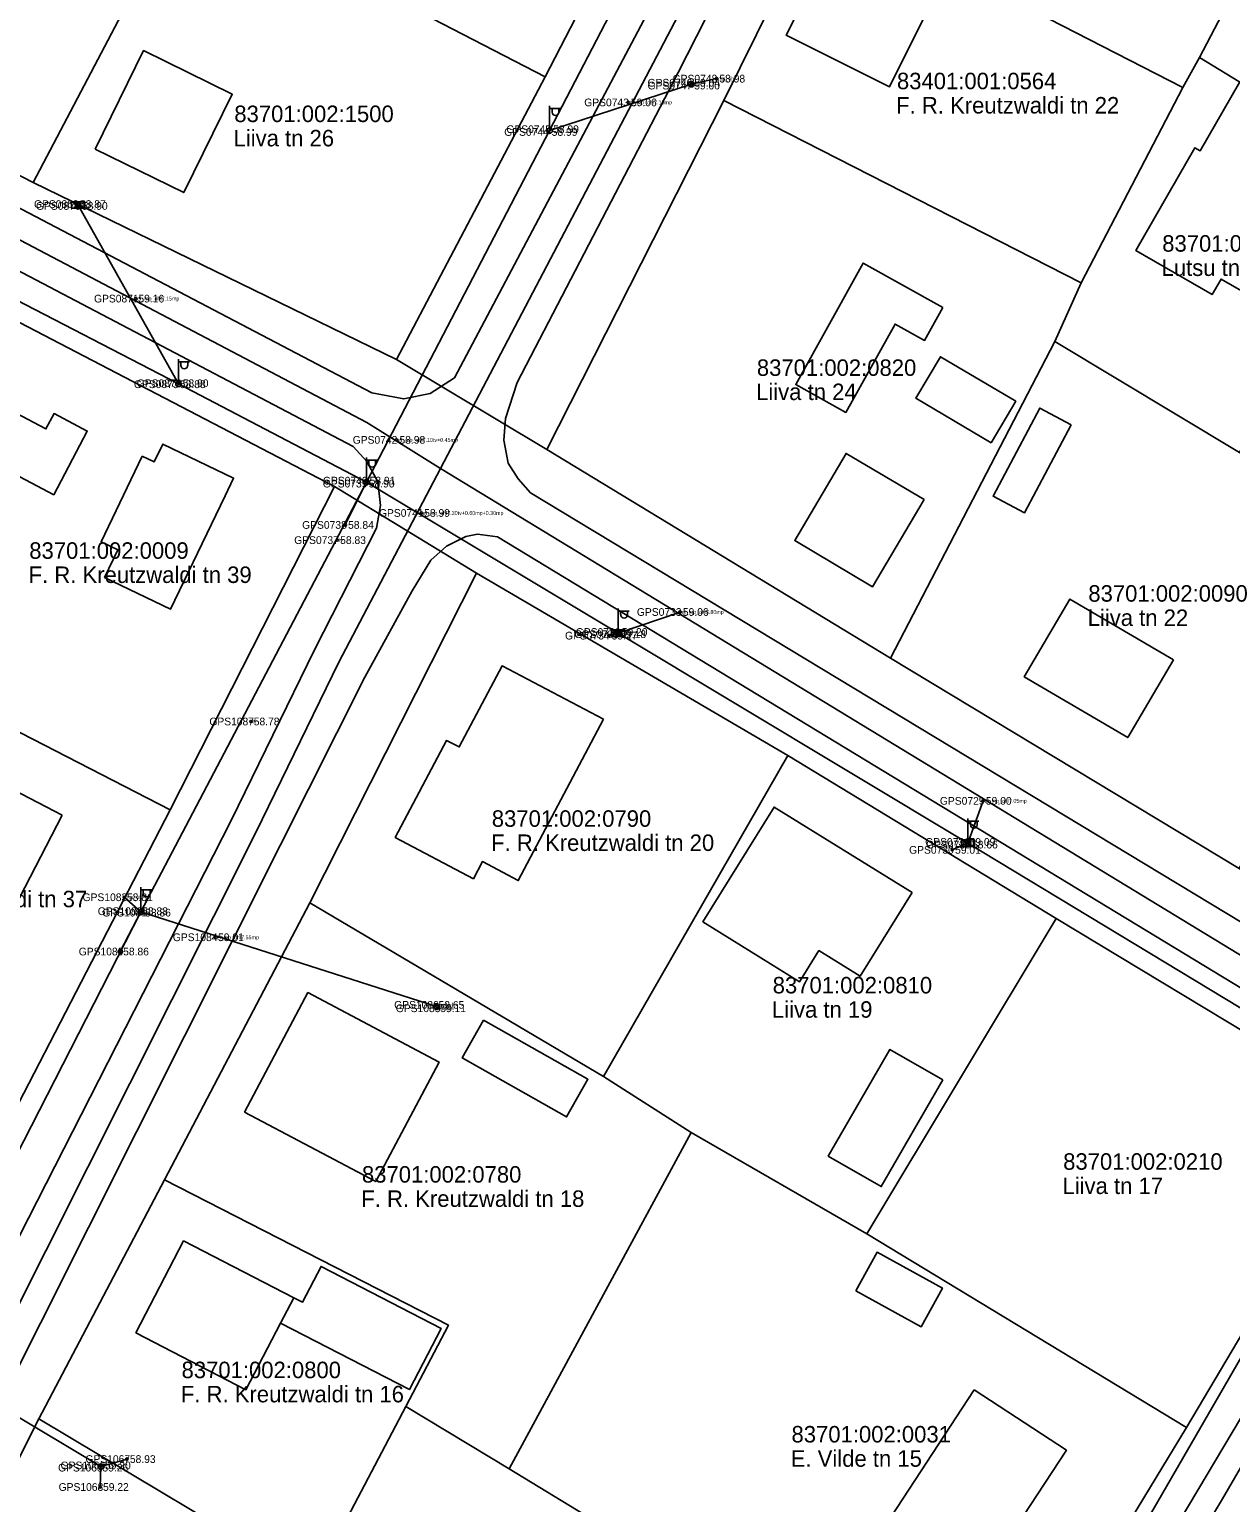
# Model space of a CAD drawing. Extents: x 580119 to 583377, y 6518915 to 6520820.
# Drawn here: x 581663.4 to 581772.7, y 6520226.6 to 6520360.6 of the extents above; entities that cross this region are included whole.
import ezdxf

# ---------------------------------------------------------------- set-up
doc = ezdxf.new("R2010")
doc.units = 0
for name, color, linetype in [('ELRAJATISMP', 7, 'Continuous'), ('Hoone Elu- või ühiskondlik hoone', 7, 'Continuous'), ('Hoone Kõrval- või tootmishoone', 7, 'Continuous'), ('L_AADRESS', 7, 'Continuous'), ('MAAMUDEL', 7, 'Continuous'), ('MOOTKORG-EH2000', 7, 'Continuous'), ('MOOTMPUNKT', 7, 'Continuous'), ('MOOTNR', 7, 'Continuous'), ('MPOHULIIN', 7, 'Continuous'), ('Muu rajatis Katusealune', 7, 'Continuous'), ('PIIR', 7, 'Continuous'), ('POST', 7, 'Continuous'), ('Rippe kõrgus', 7, 'Continuous'), ('Tee Liiklusala', 7, 'Continuous'), ('Tee Tänav Püsikate', 7, 'Continuous'), ('TUNNUS', 7, 'Continuous')]:
    doc.layers.add(name, color=color, linetype=linetype)

msp = doc.modelspace()

# ---------------------------------------------------------------- linework, layer by layer
at = {"layer": 'ELRAJATISMP'}
for p, q in [((581667.7, 6520344.94), (581667.7, 6520344.35)), ((581667.97, 6520344.94), (581667.97, 6520344.35)), ((581716.82, 6520306), (581716.82, 6520305.4)), ((581717.09, 6520306), (581717.09, 6520305.4)), ((581748.64, 6520286.88), (581748.64, 6520286.28)), ((581748.91, 6520286.88), (581748.91, 6520286.28))]:
    msp.add_line(p, q, dxfattribs=at)
for points in [[(581667.24, 6520344.94), (581668.43, 6520344.94), (581668.43, 6520344.35), (581667.24, 6520344.35)], [(581716.36, 6520306), (581717.55, 6520306), (581717.55, 6520305.4), (581716.36, 6520305.4)], [(581748.18, 6520286.88), (581749.37, 6520286.88), (581749.37, 6520286.28), (581748.18, 6520286.28)]]:
    msp.add_lwpolyline(points, close=True, dxfattribs=at)
at = {"layer": 'Hoone Elu- või ühiskondlik hoone'}
for points in [[(581737.98, 6520367.52), (581745.74, 6520363.64), (581741.64, 6520355.41), (581732.24, 6520360.09), (581734.69, 6520365), (581736.31, 6520364.19)], [(581669.38, 6520349.74), (581673.79, 6520358.69), (581681.85, 6520354.72), (581677.44, 6520345.77)], [(581782.36, 6520350.76), (581778.78, 6520344.51), (581779.52, 6520344.08), (581774.93, 6520336.1), (581771.79, 6520337.9), (581770.98, 6520336.5), (581764.04, 6520340.5), (581769.41, 6520349.85), (581769.89, 6520349.57), (581773.49, 6520355.85), (581780.48, 6520351.84)], [(581673.67, 6520321.81), (581674.76, 6520321.29), (581675.53, 6520322.89), (581681.97, 6520319.8), (581681.2, 6520318.19), (581677.44, 6520310.38), (581676.24, 6520307.88), (581670.24, 6520310.76), (581671.45, 6520313.27), (581669.92, 6520314)], [(581744.78, 6520317.84), (581740.09, 6520309.91), (581733.01, 6520314.12), (581737.69, 6520322.04)], [(581767.46, 6520303.28), (581763.31, 6520296.2), (581753.89, 6520301.73), (581758.04, 6520308.8)], [(581715.61, 6520297.87), (581707.87, 6520283.18), (581704.6, 6520284.91), (581703.79, 6520283.36), (581696.68, 6520287.11), (581701.35, 6520295.94), (581702.5, 6520295.34), (581706.4, 6520302.71)], [(581666.39, 6520289.14), (581661.53, 6520279.73), (581653.17, 6520284.04), (581655.03, 6520287.66), (581654.49, 6520287.95), (581657.49, 6520293.74)], [(581743.7, 6520282.11), (581738.97, 6520274.5), (581735.22, 6520276.82), (581733.46, 6520273.99), (581724.66, 6520279.44), (581731.14, 6520289.88)], [(581682.97, 6520262.12), (581688.73, 6520273), (581700.66, 6520266.68), (581694.9, 6520255.8)], [(581687.44, 6520245.23), (581686.25, 6520242.93), (581683.1, 6520236.86), (581673.09, 6520242.05), (581677.42, 6520250.41)], [(581749.32, 6520236.85), (581757.72, 6520231.36), (581748.53, 6520217.33), (581740.14, 6520222.82)]]:
    msp.add_lwpolyline(points, close=True, dxfattribs=at)
at = {"layer": 'Hoone Kõrval- või tootmishoone'}
for points in [[(581746.5, 6520335.33), (581744.83, 6520332.32), (581742.14, 6520333.81), (581737.67, 6520325.77), (581733.1, 6520328.31), (581739.24, 6520339.36)], [(581654.49, 6520321.57), (581657.87, 6520327.99), (581664.91, 6520324.28), (581665.64, 6520325.67), (581668.66, 6520324.08), (581665.61, 6520318.29), (581659.48, 6520321.51), (581658.42, 6520319.5)], [(581758.15, 6520324.66), (581753.9, 6520316.64), (581751.05, 6520318.15), (581755.3, 6520326.17)], [(581704.71, 6520270.48), (581714.2, 6520265.12), (581712.26, 6520261.69), (581702.77, 6520267.05)], [(581746.48, 6520265.05), (581740.88, 6520255.35), (581736.07, 6520258.13), (581741.67, 6520267.83)], [(581738.57, 6520245.87), (581740.51, 6520249.38), (581746.44, 6520246.12), (581744.51, 6520242.6)], [(581686.25, 6520242.93), (581687.44, 6520245.23), (581688.23, 6520244.82), (581689.93, 6520248.09), (581700.84, 6520242.45), (581697.96, 6520236.88)]]:
    msp.add_lwpolyline(points, close=True, dxfattribs=at)
at = {"layer": 'MOOTMPUNKT'}
for centre in [(581723.62, 6520355.77), (581725.9, 6520356.14), (581723.61, 6520355.51), (581717.86, 6520353.98), (581710.65, 6520351.29), (581710.78, 6520351.54), (581667.74, 6520344.73), (581667.92, 6520344.56), (581673.06, 6520336.13), (581676.83, 6520328.34), (581677.09, 6520328.43), (581696.8, 6520323.28), (581694.09, 6520319.57), (581694.01, 6520319.3), (581692.13, 6520315.54), (581699.05, 6520316.63), (581691.41, 6520314.16), (581722.58, 6520307.62), (581716.11, 6520305.47), (581716.89, 6520305.6), (581717.02, 6520305.8), (581683.55, 6520297.66), (581750.14, 6520290.44), (581747.34, 6520285.98), (581748.66, 6520286.7), (581748.88, 6520286.46), (581672.02, 6520281.67), (581673.4, 6520280.4), (581673.67, 6520280.27), (581680.3, 6520278.03), (581671.67, 6520276.73), (581700.36, 6520271.88), (581700.51, 6520271.57), (581669.79, 6520229.78), (581670.02, 6520229.98), (581672.28, 6520230.56), (581669.84, 6520228.02)]:
    msp.add_circle(centre, 0.1, dxfattribs=at)
at = {"layer": 'MPOHULIIN'}
for p, q in [((581676.96, 6520328.38), (581636.81, 6520349.16)), ((581673.54, 6520280.33), (581694.05, 6520319.43)), ((581716.96, 6520305.7), (581722.58, 6520307.62)), ((581716.96, 6520305.7), (581716.11, 6520305.47)), ((581669.9, 6520229.88), (581672.28, 6520230.56))]:
    msp.add_line(p, q, dxfattribs=at)
for points in [[(581710.72, 6520351.41), (581726.25, 6520381.34), (581742.11, 6520412.29)], [(581694.05, 6520319.43), (581710.72, 6520351.41), (581723.62, 6520355.64), (581725.9, 6520356.14)], [(581694.05, 6520319.43), (581676.96, 6520328.38), (581667.83, 6520344.64)], [(581815.29, 6520246.23), (581785.93, 6520264.11), (581748.77, 6520286.58), (581716.96, 6520305.7), (581694.05, 6520319.43)], [(581750.14, 6520290.44), (581748.77, 6520286.58), (581747.34, 6520285.98)], [(581672.02, 6520281.67), (581673.54, 6520280.33), (581700.43, 6520271.73)], [(581673.54, 6520280.33), (581652.91, 6520240.04), (581669.9, 6520229.88), (581669.84, 6520228.02)], [(581785.93, 6520264.11), (581785.82, 6520260.92), (581761.9, 6520219.5), (581760.01, 6520194.7), (581760.58, 6520193.81)]]:
    msp.add_lwpolyline(points, dxfattribs=at)
at = {"layer": 'Muu rajatis Katusealune'}
msp.add_lwpolyline([(581750.88, 6520323.02), (581744.04, 6520327.07), (581746.27, 6520330.84), (581753.11, 6520326.79)], close=True, dxfattribs=at)
at = {"layer": 'PIIR'}
for points in [[(581775.47, 6520450.71), (581764.63, 6520429.16), (581753.86, 6520407.85), (581744.38, 6520390.07), (581735.49, 6520372.19), (581726.57, 6520354.16), (581710.47, 6520322.41), (581696.78, 6520330.58), (581710.31, 6520356.3), (581723.68, 6520382.21), (581699.77, 6520394.19), (581699.05, 6520392.74), (581690.07, 6520397.32), (581692.57, 6520401.72), (581694.63, 6520406.35), (581703.4, 6520401.71), (581702.59, 6520399.97), (581726.4, 6520387.87), (581739.69, 6520413.76), (581752.96, 6520439.48), (581728.92, 6520451.6), (581728.2, 6520450.05), (581719.39, 6520454.49), (581721.62, 6520459.01)], [(581641.44, 6520358.2), (581663.75, 6520346.68), (581696.78, 6520330.58), (581710.47, 6520322.41), (581741.73, 6520303.41), (581773.45, 6520284.3), (581791.76, 6520272.95), (581801.15, 6520267.32), (581804.72, 6520265.17), (581827.76, 6520250.96), (581836.91, 6520245.57), (581863.22, 6520229.79), (581868.94, 6520226.76), (581900.21, 6520207.51)], [(581844.07, 6520226.32), (581821.83, 6520240.08), (581796.29, 6520255.75), (581785.75, 6520262.28), (581756.8, 6520279.75), (581732.4, 6520294.58), (581704.08, 6520311.14), (581691.15, 6520319.03), (581661.06, 6520334.72)], [(581629.73, 6520198.75), (581644.07, 6520226.93), (581626.48, 6520236.22), (581610.93, 6520241.82), (581613.05, 6520246.51), (581615.77, 6520251.05), (581623.97, 6520246.51), (581623.22, 6520244.9), (581646.85, 6520232.47), (581660.98, 6520260.16), (581676.2, 6520289.62), (581691.15, 6520319.03), (581704.08, 6520311.14), (581688.92, 6520281.17), (581675.68, 6520255.96), (581664.26, 6520234.22), (581653.01, 6520211.86)]]:
    msp.add_lwpolyline(points, dxfattribs=at)
for points in [[(581690.07, 6520397.32), (581699.05, 6520392.74), (581699.77, 6520394.19), (581723.68, 6520382.21), (581710.31, 6520356.3), (581677.65, 6520373.21)], [(581744.38, 6520390.07), (581777.64, 6520373.06), (581769.84, 6520358.07), (581768.32, 6520355.34), (581735.49, 6520372.19)], [(581769.84, 6520358.07), (581777.64, 6520373.06), (581785.47, 6520388.28), (581801.36, 6520378.94), (581785.35, 6520349.14), (581782.27, 6520350.98), (581774.1, 6520355.46)], [(581655.37, 6520384.54), (581677.65, 6520373.21), (581663.75, 6520346.68), (581641.44, 6520358.2)], [(581677.65, 6520373.21), (581710.31, 6520356.3), (581696.78, 6520330.58), (581663.75, 6520346.68)], [(581726.57, 6520354.16), (581735.49, 6520372.19), (581768.32, 6520355.34), (581759.06, 6520337.58)], [(581759.06, 6520337.58), (581768.32, 6520355.34), (581769.84, 6520358.07), (581774.1, 6520355.46), (581782.27, 6520350.98), (581785.35, 6520349.14), (581786.62, 6520345.32), (581785.55, 6520343.45), (581773.48, 6520322.14), (581756.66, 6520332.23)], [(581726.57, 6520354.16), (581759.06, 6520337.58), (581756.66, 6520332.23), (581741.73, 6520303.41), (581710.47, 6520322.41)], [(581676.2, 6520289.62), (581645.94, 6520305.18), (581661.06, 6520334.72), (581691.15, 6520319.03)], [(581773.48, 6520322.14), (581788.16, 6520313.33), (581773.45, 6520284.3), (581741.73, 6520303.41), (581756.66, 6520332.23)], [(581704.08, 6520311.14), (581732.4, 6520294.58), (581715.61, 6520265.36), (581688.92, 6520281.17)], [(581645.94, 6520305.18), (581676.2, 6520289.62), (581660.98, 6520260.16), (581631.05, 6520275.48)], [(581715.61, 6520265.36), (581732.4, 6520294.58), (581756.8, 6520279.75), (581739.56, 6520251.04), (581723.58, 6520260.27)], [(581688.92, 6520281.17), (581715.61, 6520265.36), (581723.58, 6520260.27), (581707.03, 6520229.66), (581697.63, 6520235.33), (581701.51, 6520242.74), (581675.68, 6520255.96)], [(581756.8, 6520279.75), (581785.75, 6520262.28), (581768.66, 6520233.42), (581739.56, 6520251.04)], [(581696.38, 6520086.78), (581684.97, 6520093.06), (581699.34, 6520117.41), (581709.83, 6520135.06), (581730.99, 6520170.6), (581750.36, 6520203.28), (581768.66, 6520233.42), (581785.75, 6520262.28), (581796.29, 6520255.75), (581771.2, 6520213.92), (581755.98, 6520188.75), (581745.76, 6520171.44), (581728.54, 6520142.46), (581721.29, 6520129.05)], [(581723.58, 6520260.27), (581739.56, 6520251.04), (581768.66, 6520233.42), (581750.36, 6520203.28), (581707.03, 6520229.66)], [(581675.68, 6520255.96), (581701.51, 6520242.74), (581697.63, 6520235.33), (581689.2, 6520219.3), (581664.26, 6520234.22)], [(581689.2, 6520219.3), (581697.63, 6520235.33), (581707.03, 6520229.66), (581750.36, 6520203.28), (581730.99, 6520170.6), (581680.25, 6520201.63)], [(581664.26, 6520234.22), (581689.2, 6520219.3), (581680.25, 6520201.63), (581677.87, 6520196.97), (581653.01, 6520211.86)]]:
    msp.add_lwpolyline(points, close=True, dxfattribs=at)
at = {"layer": 'POST'}
for p, q in [((581710.72, 6520351.66), (581710.72, 6520353.66)), ((581710.72, 6520353.41), (581711.72, 6520353.41)), ((581710.94, 6520353.09), (581710.94, 6520353.41)), ((581711.56, 6520353.09), (581711.56, 6520353.41)), ((581710.72, 6520351.41), (581710.72, 6520351.41)), ((581676.96, 6520328.63), (581676.96, 6520330.63)), ((581676.96, 6520330.38), (581677.96, 6520330.38)), ((581677.19, 6520330.06), (581677.19, 6520330.38)), ((581677.8, 6520330.06), (581677.8, 6520330.38)), ((581676.96, 6520328.38), (581676.96, 6520328.38)), ((581694.05, 6520319.68), (581694.05, 6520321.68)), ((581694.05, 6520321.43), (581695.05, 6520321.43)), ((581694.27, 6520321.11), (581694.27, 6520321.43)), ((581694.89, 6520321.11), (581694.89, 6520321.43)), ((581694.05, 6520319.43), (581694.05, 6520319.43)), ((581716.96, 6520305.95), (581716.96, 6520307.95)), ((581716.96, 6520307.7), (581717.96, 6520307.7)), ((581717.18, 6520307.38), (581717.18, 6520307.7)), ((581717.79, 6520307.38), (581717.79, 6520307.7)), ((581716.96, 6520305.7), (581716.96, 6520305.7)), ((581748.77, 6520286.83), (581748.77, 6520288.83)), ((581748.77, 6520288.58), (581749.77, 6520288.58)), ((581749, 6520288.26), (581749, 6520288.58)), ((581749.61, 6520288.26), (581749.61, 6520288.58)), ((581748.77, 6520286.58), (581748.77, 6520286.58)), ((581673.54, 6520280.58), (581673.54, 6520282.58)), ((581673.54, 6520282.33), (581674.54, 6520282.33)), ((581673.76, 6520282.01), (581673.76, 6520282.33)), ((581674.38, 6520282.01), (581674.38, 6520282.33)), ((581673.54, 6520280.33), (581673.54, 6520280.33))]:
    msp.add_line(p, q, dxfattribs=at)
for points in [[(581692.13, 6520315.54), (581694.05, 6520319.43)], [(581673.54, 6520280.33), (581671.67, 6520276.73)]]:
    msp.add_lwpolyline(points, dxfattribs=at)
for centre, radius in [((581723.62, 6520355.64), 0.25), ((581710.72, 6520351.41), 0.25), ((581667.83, 6520344.64), 0.25), ((581676.96, 6520328.38), 0.25), ((581694.05, 6520319.43), 0.25), ((581692.13, 6520315.54), 0.125), ((581692.13, 6520315.54), 0.105), ((581692.13, 6520315.54), 0.0851), ((581692.13, 6520315.54), 0.0651), ((581692.13, 6520315.54), 0.0451), ((581692.13, 6520315.54), 0.0251), ((581692.13, 6520315.54), 0.00511), ((581716.96, 6520305.7), 0.25), ((581748.77, 6520286.58), 0.25), ((581673.54, 6520280.33), 0.25), ((581671.67, 6520276.73), 0.2), ((581700.43, 6520271.73), 0.25), ((581669.9, 6520229.88), 0.25)]:
    msp.add_circle(centre, radius, dxfattribs=at)
for centre in [(581711.25, 6520353.09), (581677.49, 6520330.06), (581694.58, 6520321.11), (581717.49, 6520307.38), (581749.31, 6520288.26), (581674.07, 6520282.01)]:
    msp.add_arc(centre, 0.306, 180, 0, dxfattribs=at)
at = {"layer": 'Tee Liiklusala'}
for points in [[(581793.32, 6520496.68), (581771.4, 6520452.94), (581722.41, 6520356.7), (581707.77, 6520328.5), (581706.7, 6520325.22), (581706.57, 6520323.24), (581706.96, 6520321.16), (581707.86, 6520319.73), (581708.97, 6520318.47), (581787.03, 6520271.32)], [(581634.54, 6520359.01), (581694.54, 6520327.56), (581697.45, 6520327.01), (581699.85, 6520327.5), (581702.06, 6520328.93), (581726.93, 6520375.92), (581728.32, 6520378.73), (581727.22, 6520382.12), (581691.71, 6520399.86), (581692.6, 6520401.65), (581693.5, 6520403.43), (581728.08, 6520386.2), (581732.14, 6520386.2), (581750.71, 6520423.77), (581756.89, 6520435.72), (581756.1, 6520438.38), (581737.18, 6520448.54), (581720.6, 6520456.73)], [(581652.86, 6520232), (581681.76, 6520288.66), (581689.32, 6520304.19), (581694.97, 6520315.24), (581695.34, 6520317.32), (581695.09, 6520319.47), (581694.1, 6520321.3), (581692.84, 6520322.69), (581635.15, 6520352.97)], [(581731.84, 6520164.16), (581786.24, 6520255.55), (581787.38, 6520258.04), (581787.79, 6520260.36), (581787.85, 6520262.8), (581787.68, 6520264.03), (581786.95, 6520265.31), (581705.97, 6520314.45), (581704.17, 6520314.71), (581703.09, 6520314.49), (581701.33, 6520313.62), (581699.9, 6520312.34), (581698.22, 6520309.54), (581693.92, 6520301.7), (581686.24, 6520286.44), (581655.64, 6520225.53)]]:
    msp.add_lwpolyline(points, dxfattribs=at)
at = {"layer": 'Tee Tänav Püsikate'}
for points in [[(581700.8, 6520320.68), (581732.72, 6520381.57)], [(581700.8, 6520320.68), (581694.1, 6520324.85), (581633.37, 6520356.8)], [(581700.8, 6520320.68), (581691.55, 6520303.06), (581684, 6520287.55), (581653.41, 6520226.66)], [(581794.4, 6520263.72), (581700.8, 6520320.68)], [(581794.4, 6520263.72), (581784.99, 6520249.45), (581771.91, 6520226.93), (581733.57, 6520163.16), (581718.97, 6520136.73)]]:
    msp.add_lwpolyline(points, dxfattribs=at)

# ---------------------------------------------------------------- texts
at = {"layer": 'L_AADRESS'}
for s, p in [('F. R. Kreutzwaldi tn 22', (581742.24, 6520352.97)), ('Liiva tn 26', (581681.97, 6520349.98)), ('Lutsu tn 33', (581766.38, 6520338.19)), ('Liiva tn 24', (581729.5, 6520326.9)), ('F. R. Kreutzwaldi tn 39', (581663.33, 6520310.26)), ('Liiva tn 22', (581759.66, 6520306.35)), ('F. R. Kreutzwaldi tn 20', (581705.4, 6520285.88)), ('F. R. Kreutzwaldi tn 37', (581648.37, 6520280.76)), ('Liiva tn 19', (581730.94, 6520270.71)), ('Liiva tn 17', (581757.37, 6520254.67)), ('F. R. Kreutzwaldi tn 18', (581693.59, 6520253.5)), ('F. R. Kreutzwaldi tn 16', (581677.18, 6520235.72)), ('E. Vilde tn 15', (581732.65, 6520229.86))]:
    msp.add_text(s, height=1.5, dxfattribs=at).set_placement(p)
at = {"layer": 'MAAMUDEL'}
for s, p in [(' mp_ohl', (581725.9, 6520355.97)), (' tv', (581691.41, 6520313.99)), (' tv', (581683.55, 6520297.49)), (' mp_ohl', (581672.02, 6520281.49)), (' kaabel', (581700.36, 6520271.7)), (' kaabel', (581700.51, 6520271.4))]:
    msp.add_text(s, height=0.35, dxfattribs=at).set_placement(p)
at = {"layer": 'MOOTKORG-EH2000'}
for s, p in [(' 59.04', (581723.62, 6520355.42)), (' 59.00', (581723.61, 6520355.16)), (' 58.98', (581725.9, 6520355.79)), (' 59.06', (581717.86, 6520353.63)), (' 58.99', (581710.78, 6520351.19)), (' 58.99', (581710.65, 6520350.94)), (' 58.87', (581667.74, 6520344.38)), (' 58.90', (581667.92, 6520344.21)), (' 59.16', (581673.06, 6520335.78)), (' 58.88', (581676.83, 6520327.99)), (' 58.90', (581677.09, 6520328.08)), (' 58.98', (581696.8, 6520322.93)), (' 58.90', (581694.01, 6520318.95)), (' 58.91', (581694.09, 6520319.22)), (' 58.99', (581699.05, 6520316.28)), (' 58.84', (581692.13, 6520315.19)), (' 58.83', (581691.41, 6520313.81)), (' 59.06', (581722.58, 6520307.27)), (' 59.20', (581717.02, 6520305.45)), (' 59.17', (581716.11, 6520305.12)), (' 59.18', (581716.89, 6520305.25)), (' 58.78', (581683.55, 6520297.31)), (' 59.00', (581750.14, 6520290.09)), (' 59.01', (581747.34, 6520285.63)), (' 59.09', (581748.66, 6520286.35)), (' 58.66', (581748.88, 6520286.11)), (' 58.81', (581672.02, 6520281.32)), (' 58.83', (581673.4, 6520280.05)), (' 58.86', (581673.67, 6520279.92)), (' 59.01', (581680.3, 6520277.68)), (' 58.86', (581671.67, 6520276.38)), (' 59.65', (581700.36, 6520271.53)), (' 59.11', (581700.51, 6520271.22)), (' 59.26', (581669.79, 6520229.43)), (' 59.20', (581670.02, 6520229.63)), (' 58.93', (581672.28, 6520230.21)), (' 59.22', (581669.84, 6520227.67))]:
    msp.add_text(s, height=0.7, dxfattribs=at).set_placement(p)
at = {"layer": 'MOOTNR'}
for s, p in [('GPS0746 ', (581719.63, 6520355.42)), ('GPS0747 ', (581719.63, 6520355.16)), ('GPS0748 ', (581721.91, 6520355.79)), ('GPS0743 ', (581713.87, 6520353.63)), ('GPS0745 ', (581706.79, 6520351.19)), ('GPS0744 ', (581706.59, 6520350.94)), ('GPS0869 ', (581663.82, 6520344.38)), ('GPS0870 ', (581664, 6520344.21)), ('GPS0871 ', (581669.28, 6520335.78)), ('GPS0873 ', (581672.91, 6520327.99)), ('GPS0872 ', (581673.17, 6520328.08)), ('GPS0742 ', (581692.81, 6520322.93)), ('GPS0739 ', (581690.09, 6520318.95)), ('GPS0740 ', (581690.1, 6520319.22)), ('GPS0741 ', (581695.2, 6520316.28)), ('GPS0738 ', (581688.21, 6520315.19)), ('GPS0737 ', (581687.49, 6520313.81)), ('GPS0733 ', (581718.66, 6520307.27)), ('GPS0736 ', (581713.1, 6520305.45)), ('GPS0734 ', (581712.12, 6520305.12)), ('GPS0735 ', (581712.97, 6520305.25)), ('GPS1087 ', (581679.77, 6520297.31)), ('GPS0729 ', (581746.22, 6520290.09)), ('GPS0730 ', (581743.42, 6520285.63)), ('GPS0731 ', (581744.88, 6520286.35)), ('GPS0732 ', (581744.96, 6520286.11)), ('GPS1083 ', (581668.24, 6520281.32)), ('GPS1082 ', (581669.62, 6520280.05)), ('GPS1081 ', (581670.03, 6520279.92)), ('GPS1084 ', (581676.45, 6520277.68)), ('GPS1080 ', (581667.89, 6520276.38)), ('GPS1086 ', (581696.58, 6520271.53)), ('GPS1085 ', (581696.73, 6520271.22)), ('GPS1065 ', (581666.01, 6520229.43)), ('GPS1066 ', (581666.24, 6520229.63)), ('GPS1067 ', (581668.5, 6520230.21)), ('GPS1068 ', (581666.06, 6520227.67))]:
    msp.add_text(s, height=0.7, dxfattribs=at).set_placement(p)
at = {"layer": 'Rippe kõrgus'}
for s, p in [(' el_mp_ohl7.15mp', (581717.86, 6520353.81)), (' el_mp_ohl7.15mp', (581673.06, 6520335.96)), (' el_mp_ohl7.10tv+0.45mp', (581696.8, 6520323.1)), (' el_mp_ohl7.30tv+0.60mp+0.30mp', (581699.05, 6520316.45)), (' el_mp_ohl5.80mp', (581722.58, 6520307.44)), (' el_mp_ohl7.05mp', (581750.14, 6520290.26)), (' el_mp_ohl7.55mp', (581680.3, 6520277.85))]:
    msp.add_text(s, height=0.35, dxfattribs=at).set_placement(p)
at = {"layer": 'TUNNUS'}
for s, p in [('83401:001:0564', (581742.31, 6520355.18)), ('83701:002:1500', (581682.04, 6520352.19)), ('83701:002:0400', (581766.44, 6520340.4)), ('83701:002:0820', (581729.57, 6520329.1)), ('83701:002:0009', (581663.39, 6520312.46)), ('83701:002:0090', (581759.72, 6520308.56)), ('83701:002:0790', (581705.46, 6520288.08)), ('83701:002:0810', (581731.01, 6520272.92)), ('83701:002:0210', (581757.43, 6520256.88)), ('83701:002:0780', (581693.65, 6520255.71)), ('83701:002:0800', (581677.24, 6520237.92)), ('83701:002:0031', (581732.72, 6520232.07))]:
    msp.add_text(s, height=1.5, dxfattribs=at).set_placement(p)

doc.saveas('drawing.dxf')
